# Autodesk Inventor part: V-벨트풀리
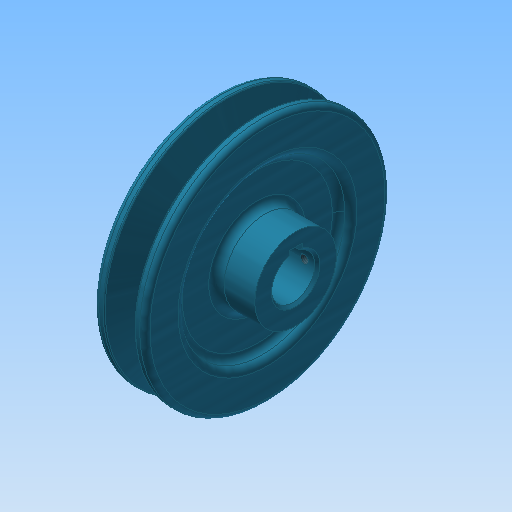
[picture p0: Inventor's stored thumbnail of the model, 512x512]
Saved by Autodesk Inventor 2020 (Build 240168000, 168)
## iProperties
Created: 2015-09
Part Number: V-벨트풀리
Material: 강철, 연강
Document SubType Name: Modeling
Designer: mduedu
Density: 7.86 g/cm^3
Mass: 779.014 g
Surface Area: 277.465 cm^2
Volume: 99.1112 cm^3
Appearance: 강철
Author: mduedu
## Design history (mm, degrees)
sketch "스케치1"
  geometry: L1 (-10, 0)-(10, 0); L2 (-10, 0)-(-10, 48); L3 (-10, 48)-(-5.976, 48); L4 (-5.976, 48)-(-2.154, 35.5); L5 (-2.154, 35.5)-(2.154, 35.5); L6 (2.154, 35.5)-(5.976, 48); L7 (5.976, 48)-(10, 48); L8 (10, 48)-(10, 0); L9 (0, 0)-(0, 35.5); L10 (-10, 43.5)-(10, 43.5); 3 further points
  constraints: 20 end point, 6 point on line, 3 perpendicular, 2 midpoint, 2 parallel, 2 symmetric about line, 1 coincident, 1 collinear, 1 equal length, 1 horizontal, 1 vertical, 1 vertical alignment
  dimensions: "d0" = 20 distance between parallel lines of L8 L2; "d2" = 96 diameter of L3 L1; "d3" = 87 diameter of L10 L1; "d4" = 4.5 distance between parallel lines of L10 L3 (derived); "d5" = 8 distance between parallel lines of L5 L10; "d6" = 9.2 distance of point (4.6, 43.5) point (-4.6, 43.5); "d7" = 34 deg angle of L6 L4
revolve "회전1" sketch "스케치1" stored, may be unused: angle "d8" = 90 deg
sketch "스케치2"
  geometry: C1 r 16 at (0, 0); 1 further point
  constraints: 1 centre point, 1 coincident
  dimensions: "d9" = 32 diameter of C1
extrude "돌출1" join sketch "스케치2" distance "d10" = 11; taper "d11" = 0 deg
fillet "모깎기1" dims "d12" = 1, "d13" = 0.5, "d14" = 2
sketch "스케치3"
  geometry: C1 r 16 at (0, 0) reference; C2 r 32 at (0, 0); 1 further point
  constraints: 1 centre point, 1 coincident
  dimensions: "d15" = 64 diameter of C2
extrude "돌출2" cut sketch "스케치3" distance "d16" = 4; taper "d17" = 0 deg
fillet "모깎기2" dims "d18" = 3
fillet "모깎기3" dims "d19" = 3
fillet "모깎기4" dims "d20" = 3
sketch "스케치4"
  geometry: C1 r 8.5 at (0, 0); 1 further point
  constraints: 1 centre point, 1 coincident
  dimensions: "d21" = 17 diameter of C1
extrude "돌출3" cut sketch "스케치4" extent not by distance; stored distance "d22" = 4; taper "d23" = 0 deg
sketch "스케치5"
  geometry: L1 (-2.5, 8.124)-(2.5, 8.124); L2 (2.5, 8.124)-(2.5, 10.8); L3 (2.5, 10.8)-(-2.5, 10.8); L4 (-2.5, 10.8)-(-2.5, 8.124); A1 r 8.5 centre (0, 0) between (-2.5, 8.124) and (2.5, 8.124) reference; 2 further points
  constraints: 8 end point, 3 point on circle, 2 parallel, 1 horizontal, 1 perpendicular, 1 vertical alignment
  dimensions: "d24" = 5 distance of L2.end L3.end; "d26" = 19.3 distance from line of L3 point (0, -8.5)
extrude "돌출4" cut sketch "스케치5" extent not by distance; stored distance "d27" = 4; taper "d28" = 0 deg
chamfer "모따기1" distance "d29" = 1; stored, may be unused: second distance "d30" = 2, angle "d31" = 45 deg
node "작업 평면1"
sketch "스케치6"
  geometry: L1 (-11, 16)-(-11, -16) reference; 2 further points
  constraints: 1 horizontal alignment
  dimensions: "d32" = 5 distance from line of point (-6, 0) L1
hole "구멍1" sketch "스케치6" at (-6, 0) diameter "d33" = 3.242; stored, may be unused: countersink angle "d37" = 90 deg, drill point angle "d39" = 118 deg; dims "d34" = 6, "d35" = 4, "d36" = 2, "d38" = 8
node "솔리드1"
mirror "대칭1"
